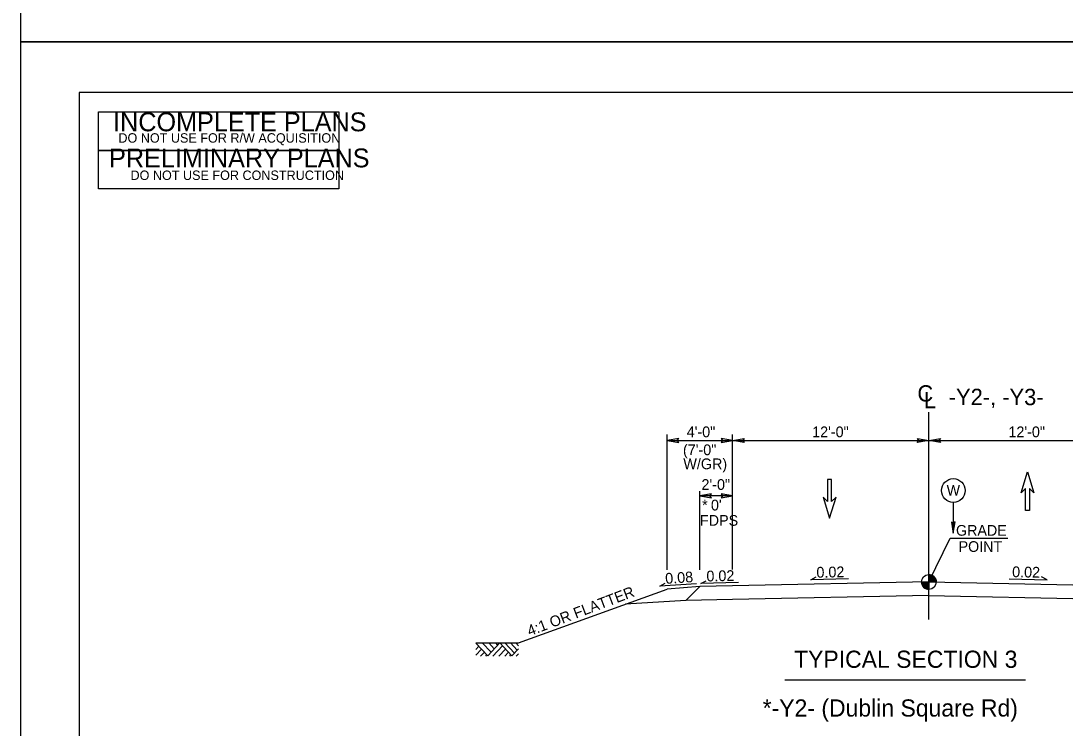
# Model space of a CAD drawing. Extents: x 1901670 to 1902225, y 193498 to 194278.
# Drawn here: x 1901670 to 1901733.8, y 194060.4 to 194103.6 of the extents above; entities that cross this region are included whole.
import ezdxf

# ---------------------------------------------------------------- set-up
doc = ezdxf.new("R2010")
doc.units = 0
for name, color, linetype in [('Old_Level_1', 7, 'Continuous'), ('Old_Level_10', 7, 'Continuous'), ('Old_Level_11', 7, 'Continuous'), ('Old_Level_2', 7, 'Continuous'), ('Old_Level_20', 7, 'Continuous'), ('Prop Dimension', 7, 'Continuous'), ('Prop Dimension Text', 7, 'Continuous'), ('Scratch_Level_0', 7, 'Continuous'), ('Sheet Sticker Incomplete CELL', 7, 'Continuous'), ('Sheet Sticker Preliminary CELL', 7, 'Continuous'), ('Typical Pavement Slope CELL', 7, 'Continuous'), ('Typical Terminator CELL', 7, 'Continuous'), ('Typical Text Grade Point CELL', 7, 'Continuous')]:
    doc.layers.add(name, color=color, linetype=linetype)

# ---------------------------------------------------------------- blocks, each defined once
blk = doc.blocks.new('TERMINATOR')
at = {"layer": 'Typical Terminator CELL'}
blk.add_lwpolyline([(-0.469, 0.081), (0, 0), (-0.471, -0.083), (-0.411, 0)], close=True, dxfattribs=at)

msp = doc.modelspace()

# ---------------------------------------------------------------- linework, layer by layer
at = {"layer": 'Old_Level_1'}
for p, q in [((1901725.482, 194067.001), (1901725.482, 194079.677)), ((1901709.482, 194070.042), (1901709.482, 194078.317)), ((1901711.482, 194070.042), (1901711.482, 194074.843)), ((1901718.259, 194069.439), (1901718.592, 194069.606)), ((1901720.574, 194069.488), (1901718.259, 194069.439)), ((1901725.482, 194069.297), (1901725.482, 194069.747)), ((1901730.39, 194069.488), (1901732.705, 194069.439)), ((1901732.705, 194069.439), (1901732.372, 194069.606)), ((1901709.034, 194069.047), (1901709.36, 194069.228)), ((1901711.27, 194069.192), (1901709.034, 194069.047)), ((1901711.482, 194069.017), (1901709.482, 194068.85)), ((1901710.631, 194068.166), (1901711.482, 194069.017)), ((1901713.482, 194069.057), (1901711.482, 194069.017)), ((1901711.532, 194069.21), (1901711.865, 194069.377)), ((1901713.847, 194069.259), (1901711.532, 194069.21)), ((1901725.482, 194069.297), (1901713.482, 194069.057)), ((1901725.032, 194069.297), (1901725.482, 194069.297)), ((1901725.481, 194068.847), (1901725.482, 194069.297)), ((1901725.482, 194069.297), (1901725.481, 194068.847)), ((1901725.932, 194069.297), (1901725.482, 194069.297)), ((1901725.482, 194069.297), (1901737.482, 194069.057)), ((1901713.482, 194068.223), (1901710.631, 194068.166)), ((1901725.482, 194068.463), (1901713.482, 194068.223)), ((1901725.465, 194068.463), (1901737.482, 194068.223)), ((1901710.631, 194068.166), (1901706.944, 194067.936)), ((1901697.789, 194065.566), (1901698.513, 194064.787)), ((1901697.789, 194065.165), (1901697.975, 194065.365)), ((1901697.789, 194064.832), (1901698.131, 194065.198)), ((1901698.077, 194064.769), (1901698.304, 194065.012)), ((1901698.18, 194065.574), (1901698.713, 194065.001)), ((1901698.513, 194064.787), (1901699.244, 194065.573)), ((1901698.578, 194065.574), (1901698.911, 194065.215)), ((1901698.823, 194064.769), (1901699.409, 194065.397)), ((1901698.98, 194065.574), (1901699.113, 194065.431)), ((1901699.193, 194064.769), (1901699.593, 194065.198)), ((1901699.244, 194065.573), (1901699.985, 194064.777)), ((1901699.559, 194064.769), (1901699.776, 194065.002)), ((1901699.566, 194065.574), (1901700.146, 194064.951)), ((1901699.899, 194065.574), (1901700.313, 194065.13)), ((1901699.985, 194064.777), (1901700.389, 194065.212)), ((1901700.219, 194065.574), (1901700.389, 194065.391)), ((1901698.388, 194064.769), (1901698.459, 194064.845)), ((1901699.854, 194064.769), (1901699.923, 194064.843)), ((1901700.255, 194064.769), (1901700.389, 194064.912)), ((1901716.679, 194063.325), (1901731.393, 194063.325))]:
    msp.add_line(p, q, dxfattribs=at)
for points in [[(1901725.486, 194069.747), (1901725.486, 194069.747), (1901725.486, 194069.297)], [(1901725.495, 194069.747), (1901725.495, 194069.297)], [(1901725.504, 194069.746), (1901725.504, 194069.297)], [(1901725.513, 194069.746), (1901725.513, 194069.297)], [(1901725.522, 194069.745), (1901725.522, 194069.297)], [(1901725.531, 194069.744), (1901725.531, 194069.297)], [(1901725.54, 194069.743), (1901725.54, 194069.297)], [(1901725.549, 194069.742), (1901725.549, 194069.297)], [(1901725.558, 194069.741), (1901725.558, 194069.297)], [(1901725.567, 194069.739), (1901725.567, 194069.297)], [(1901725.576, 194069.737), (1901725.576, 194069.297)], [(1901725.585, 194069.735), (1901725.585, 194069.297)], [(1901725.594, 194069.733), (1901725.594, 194069.297)], [(1901725.603, 194069.73), (1901725.603, 194069.297)], [(1901725.612, 194069.728), (1901725.612, 194069.297)], [(1901725.621, 194069.725), (1901725.621, 194069.297)], [(1901725.63, 194069.722), (1901725.63, 194069.297)], [(1901725.639, 194069.719), (1901725.639, 194069.297)], [(1901725.648, 194069.715), (1901725.648, 194069.297)], [(1901725.657, 194069.711), (1901725.657, 194069.297)], [(1901725.666, 194069.707), (1901725.666, 194069.297)], [(1901725.675, 194069.703), (1901725.675, 194069.297)], [(1901725.684, 194069.699), (1901725.684, 194069.297)], [(1901725.693, 194069.694), (1901725.693, 194069.297)], [(1901725.702, 194069.689), (1901725.702, 194069.297)], [(1901725.711, 194069.684), (1901725.711, 194069.297)], [(1901725.72, 194069.679), (1901725.72, 194069.297)], [(1901725.729, 194069.673), (1901725.729, 194069.297)], [(1901725.738, 194069.667), (1901725.738, 194069.297)], [(1901725.747, 194069.66), (1901725.747, 194069.297)], [(1901725.756, 194069.654), (1901725.756, 194069.297)], [(1901725.765, 194069.647), (1901725.765, 194069.297)], [(1901725.774, 194069.639), (1901725.774, 194069.297)], [(1901725.783, 194069.631), (1901725.783, 194069.297)], [(1901725.792, 194069.623), (1901725.792, 194069.297)], [(1901725.801, 194069.614), (1901725.801, 194069.297)], [(1901725.81, 194069.605), (1901725.81, 194069.297)], [(1901725.819, 194069.595), (1901725.819, 194069.297)], [(1901725.828, 194069.584), (1901725.828, 194069.297)], [(1901725.837, 194069.573), (1901725.837, 194069.297)], [(1901725.846, 194069.561), (1901725.846, 194069.297)], [(1901725.855, 194069.548), (1901725.855, 194069.297)], [(1901725.864, 194069.534), (1901725.864, 194069.297)], [(1901725.873, 194069.519), (1901725.873, 194069.297)], [(1901725.882, 194069.503), (1901725.882, 194069.297)], [(1901725.891, 194069.484), (1901725.891, 194069.297)], [(1901725.034, 194069.297), (1901725.034, 194069.248)], [(1901725.043, 194069.297), (1901725.043, 194069.195)], [(1901725.052, 194069.297), (1901725.052, 194069.163)], [(1901725.061, 194069.297), (1901725.061, 194069.136)], [(1901725.07, 194069.297), (1901725.07, 194069.115)], [(1901725.079, 194069.297), (1901725.079, 194069.096)], [(1901725.088, 194069.297), (1901725.088, 194069.079)], [(1901725.097, 194069.297), (1901725.097, 194069.063)], [(1901725.106, 194069.297), (1901725.106, 194069.049)], [(1901725.115, 194069.297), (1901725.115, 194069.036)], [(1901725.124, 194069.297), (1901725.124, 194069.024)], [(1901725.133, 194069.297), (1901725.133, 194069.013)], [(1901725.142, 194069.297), (1901725.142, 194069.002)], [(1901725.151, 194069.297), (1901725.151, 194068.992)], [(1901725.16, 194069.297), (1901725.16, 194068.982)], [(1901725.169, 194069.297), (1901725.169, 194068.973)], [(1901725.178, 194069.297), (1901725.178, 194068.965)], [(1901725.187, 194069.297), (1901725.187, 194068.957)], [(1901725.196, 194069.297), (1901725.196, 194068.949)], [(1901725.205, 194069.297), (1901725.205, 194068.942)], [(1901725.214, 194069.297), (1901725.214, 194068.935)], [(1901725.223, 194069.297), (1901725.223, 194068.929)], [(1901725.232, 194069.297), (1901725.232, 194068.923)], [(1901725.241, 194069.297), (1901725.241, 194068.917)], [(1901725.25, 194069.297), (1901725.25, 194068.911)], [(1901725.259, 194069.297), (1901725.259, 194068.906)], [(1901725.268, 194069.297), (1901725.268, 194068.901)], [(1901725.277, 194069.297), (1901725.277, 194068.896)], [(1901725.286, 194069.297), (1901725.286, 194068.892)], [(1901725.295, 194069.297), (1901725.295, 194068.888)], [(1901725.304, 194069.297), (1901725.304, 194068.884)], [(1901725.313, 194069.297), (1901725.313, 194068.88)], [(1901725.322, 194069.297), (1901725.322, 194068.876)], [(1901725.331, 194069.297), (1901725.331, 194068.873)], [(1901725.34, 194069.297), (1901725.34, 194068.87)], [(1901725.349, 194069.297), (1901725.349, 194068.867)], [(1901725.358, 194069.297), (1901725.358, 194068.865)], [(1901725.367, 194069.297), (1901725.367, 194068.862)], [(1901725.376, 194069.297), (1901725.376, 194068.86)], [(1901725.385, 194069.297), (1901725.385, 194068.858)], [(1901725.394, 194069.297), (1901725.394, 194068.856)], [(1901725.403, 194069.297), (1901725.403, 194068.854)], [(1901725.412, 194069.297), (1901725.412, 194068.853)], [(1901725.421, 194069.297), (1901725.421, 194068.851)], [(1901725.43, 194069.297), (1901725.43, 194068.85)], [(1901725.439, 194069.297), (1901725.439, 194068.849)], [(1901725.448, 194069.297), (1901725.448, 194068.848)], [(1901725.457, 194069.297), (1901725.457, 194068.848)], [(1901725.466, 194069.297), (1901725.466, 194068.847)], [(1901725.475, 194069.297), (1901725.475, 194068.847), (1901725.475, 194068.847)], [(1901725.9, 194069.463), (1901725.9, 194069.297)], [(1901725.909, 194069.438), (1901725.909, 194069.297)], [(1901725.918, 194069.407), (1901725.918, 194069.297)], [(1901725.927, 194069.361), (1901725.927, 194069.297)], [(1901697.789, 194065.574), (1901700.389, 194065.574)]]:
    msp.add_lwpolyline(points, dxfattribs=at)
msp.add_circle((1901725.481, 194069.297), 0.45, dxfattribs=at)
for start, end in [(359.99048, 89.99048), (179.99048, 269.99048)]:
    msp.add_arc((1901725.481, 194069.297), 0.45, start, end, dxfattribs=at)
at = {"layer": 'Old_Level_10'}
msp.add_lwpolyline([(1901673.525, 194019.872), (1901776.645, 194019.872), (1901776.645, 194099.208), (1901673.525, 194099.208)], close=True, dxfattribs=at)
at = {"layer": 'Old_Level_11'}
msp.add_line((1901726.977, 194074.163), (1901726.977, 194072.289), dxfattribs=at)
msp.add_lwpolyline([(1901726.861, 194072.96), (1901726.977, 194072.289), (1901727.096, 194072.964), (1901726.977, 194072.878)], close=True, dxfattribs=at)
msp.add_circle((1901726.977, 194074.888), 0.725, dxfattribs=at)
at = {"layer": 'Prop Dimension'}
for p, q in [((1901713.482, 194070.625), (1901713.482, 194078.317)), ((1901713.482, 194077.947), (1901725.482, 194077.947)), ((1901725.482, 194077.947), (1901737.482, 194077.947))]:
    msp.add_line(p, q, dxfattribs=at)
for points in [[(1901731.907, 194074.755), (1901731.636, 194075.005), (1901731.636, 194073.671), (1901731.386, 194073.671), (1901731.386, 194075.005), (1901731.116, 194074.755), (1901731.511, 194076.026)], [(1901731.907, 194074.755), (1901731.636, 194075.005), (1901731.636, 194073.671), (1901731.386, 194073.671), (1901731.386, 194075.005), (1901731.116, 194074.755), (1901731.511, 194076.026)], [(1901719.806, 194074.477), (1901719.535, 194074.227), (1901719.535, 194075.56), (1901719.285, 194075.56), (1901719.285, 194074.227), (1901719.015, 194074.477), (1901719.41, 194073.206)], [(1901719.806, 194074.477), (1901719.535, 194074.227), (1901719.535, 194075.56), (1901719.285, 194075.56), (1901719.285, 194074.227), (1901719.015, 194074.477), (1901719.41, 194073.206)]]:
    msp.add_lwpolyline(points, close=True, dxfattribs=at)
at = {"layer": 'Prop Dimension Text'}
for p, q in [((1901709.482, 194077.947), (1901713.482, 194077.947)), ((1901713.482, 194070.057), (1901713.482, 194078.317)), ((1901709.482, 194070.042), (1901709.482, 194074.843)), ((1901713.482, 194074.561), (1901711.482, 194074.561))]:
    msp.add_line(p, q, dxfattribs=at)
at = {"layer": 'Scratch_Level_0'}
for points in [[(1901669.969, 194187.31), (1901779.969, 194187.31), (1901779.969, 194102.31), (1901669.969, 194102.31)], [(1901669.969, 194102.31), (1901779.969, 194102.31), (1901779.969, 194017.31), (1901669.969, 194017.31)]]:
    msp.add_lwpolyline(points, close=True, dxfattribs=at)
at = {"layer": 'Sheet Sticker Incomplete CELL'}
msp.add_lwpolyline([(1901674.711, 194095.674), (1901674.711, 194098.024), (1901689.411, 194098.024), (1901689.411, 194095.674)], close=True, dxfattribs=at)
at = {"layer": 'Sheet Sticker Preliminary CELL'}
msp.add_lwpolyline([(1901674.711, 194093.324), (1901674.711, 194095.674), (1901689.411, 194095.674), (1901689.411, 194093.324)], close=True, dxfattribs=at)
at = {"layer": 'Typical Pavement Slope CELL'}
msp.add_line((1901700.389, 194065.574), (1901709.482, 194068.85), dxfattribs=at)
at = {"layer": 'Typical Text Grade Point CELL'}
for p, q in [((1901725.482, 194069.297), (1901726.777, 194071.97)), ((1901726.777, 194071.97), (1901730.315, 194071.97))]:
    msp.add_line(p, q, dxfattribs=at)

# ---------------------------------------------------------------- block references
at = {"layer": 'Prop Dimension', "xscale": 1.5, "rotation": 180}
for p, yscale in [((1901709.482, 194077.947), -1.5), ((1901713.482, 194077.947), 1.5), ((1901725.482, 194077.947), 1.5), ((1901711.482, 194074.561), -1.5)]:
    msp.add_blockref('TERMINATOR', p, dxfattribs=dict(at, yscale=yscale))
at = {"layer": 'Prop Dimension', "xscale": 1.5}
for p, yscale in [((1901713.482, 194077.947), -1.5), ((1901725.482, 194077.947), 1.5), ((1901713.482, 194074.561), -1.5)]:
    msp.add_blockref('TERMINATOR', p, dxfattribs=dict(at, yscale=yscale))

# ---------------------------------------------------------------- texts
at = {"layer": 'Old_Level_1'}
msp.add_text('4:1 OR FLATTER', height=0.656, rotation=20.83423, dxfattribs=at).set_placement((1901701.075, 194065.978))
msp.add_text('TYPICAL SECTION 3', height=1.05, dxfattribs=at).set_placement((1901717.24, 194064.051))
at = {"layer": 'Old_Level_2'}
msp.add_text('C', height=1, dxfattribs=at).set_placement((1901724.78, 194080.323))
for s, height, rotation, p in [('-Y2-, -Y3-', 1, 359.9469, (1901726.697, 194080.11)), ('L', 1, 359.9469, (1901725.182, 194079.919)), ('0.02', 0.656, 1.19158, (1901718.614, 194069.558)), ('0.02', 0.656, 358.80842, (1901730.567, 194069.595)), ('0.08', 0.656, 3.71657, (1901709.384, 194069.181)), ('0.02', 0.656, 1.19158, (1901711.888, 194069.329))]:
    msp.add_text(s, height=height, rotation=rotation, dxfattribs=at).set_placement(p)
at = {"layer": 'Old_Level_20'}
msp.add_text('W', height=0.649, dxfattribs=at).set_placement((1901726.568, 194074.582))
at = {"layer": 'Prop Dimension'}
for p in [(1901718.345, 194078.145), (1901730.345, 194078.145)]:
    msp.add_text('12\'-0" ', height=0.656, dxfattribs=at).set_placement(p)
at = {"layer": 'Prop Dimension Text'}
for s, height, p in [('4\'-0"', 0.656, (1901710.675, 194078.145)), ('(7\'-0" ', 0.656, (1901710.448, 194077.049)), ('W/GR)', 0.656, (1901710.469, 194076.189)), ('2\'-0"', 0.656, (1901711.579, 194074.926)), ('*', 0.656, (1901711.619, 194073.669)), ("0'", 0.656, (1901712.158, 194073.669)), ('FDPS', 0.656, (1901711.485, 194072.735)), ('*-Y2- (Dublin Square Rd) ', 1.05, (1901715.319, 194061.072))]:
    msp.add_text(s, height=height, dxfattribs=at).set_placement(p)
at = {"layer": 'Sheet Sticker Incomplete CELL'}
for s, height, p in [('INCOMPLETE PLANS', 1.152, (1901675.606, 194096.844)), ('DO NOT USE FOR R/W ACQUISITION', 0.576, (1901675.931, 194096.149))]:
    msp.add_text(s, height=height, dxfattribs=at).set_placement(p)
at = {"layer": 'Sheet Sticker Preliminary CELL'}
for s, height, p in [('PRELIMINARY PLANS', 1.152, (1901675.361, 194094.639)), ('DO NOT USE FOR CONSTRUCTION', 0.576, (1901676.671, 194093.869))]:
    msp.add_text(s, height=height, dxfattribs=at).set_placement(p)
at = {"layer": 'Typical Text Grade Point CELL'}
for s, p in [('GRADE', (1901727.141, 194072.126)), ('POINT', (1901727.298, 194071.137))]:
    msp.add_text(s, height=0.6525, dxfattribs=at).set_placement(p)

doc.saveas('drawing.dxf')
